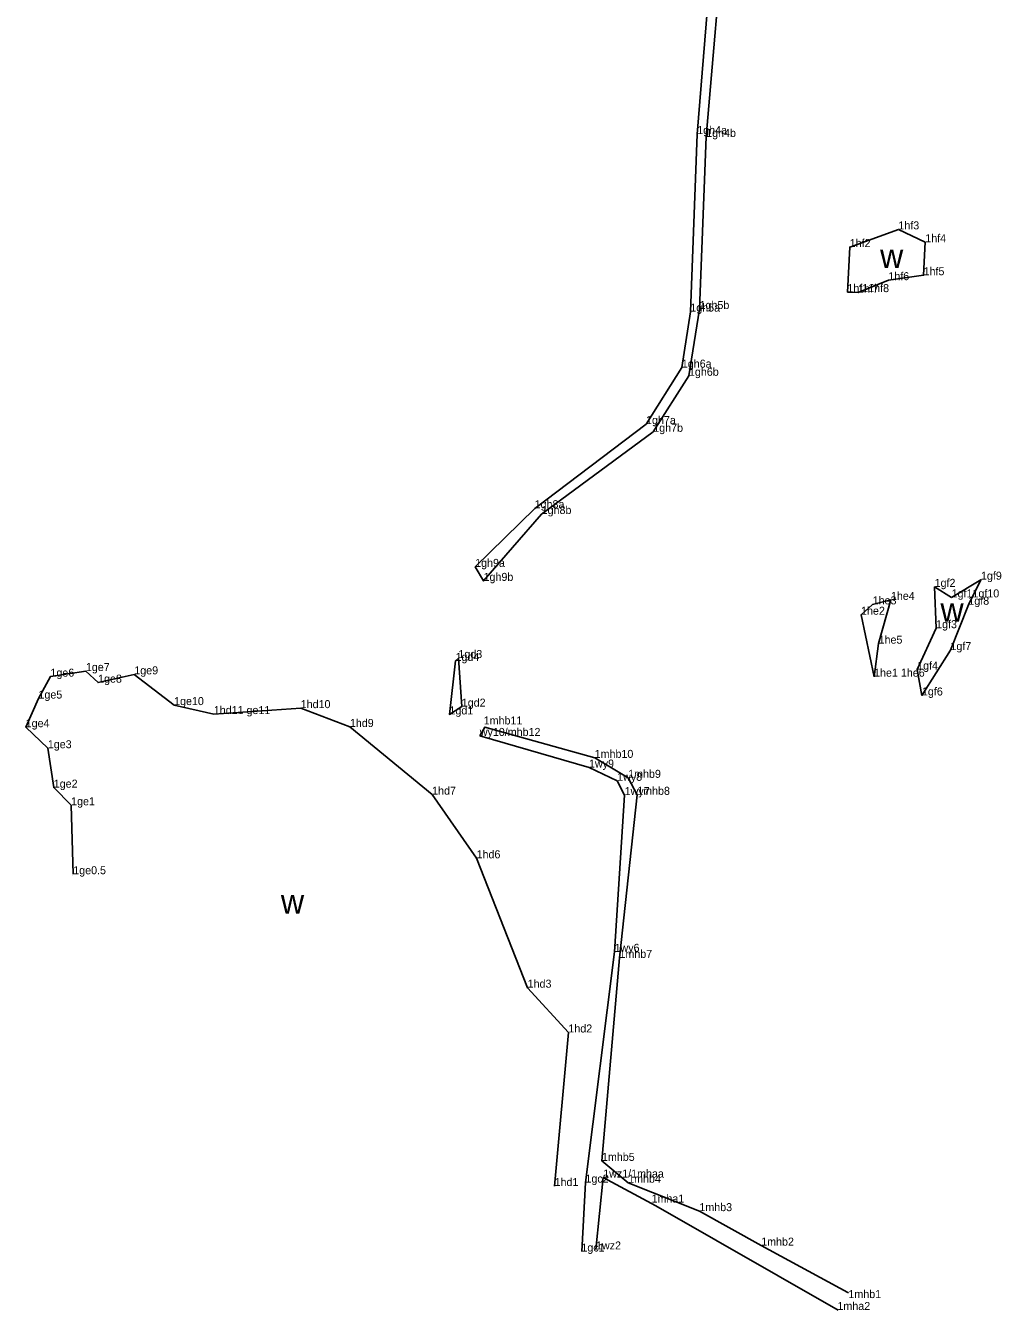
# Model space of a CAD drawing. Extents: x 2072529 to 2267990, y 436423 to 470008.
# Drawn here: x 2077727 to 2078337, y 465348 to 466151 of the extents above; entities that cross this region are included whole.
import ezdxf

# ---------------------------------------------------------------- set-up
doc = ezdxf.new("R2010")
doc.units = 0
for name, color, linetype in [('Level 3', 7, 'Continuous'), ('Old_Level_52', 7, 'Continuous'), ('Prop SS Cut Line', 7, 'Continuous')]:
    doc.layers.add(name, color=color, linetype=linetype)

msp = doc.modelspace()

# ---------------------------------------------------------------- linework, layer by layer
at = {"layer": 'Level 3'}
for p, q in [((2078147.017, 466082.829), (2078147.017, 466082.829)), ((2078152.623, 466081.039), (2078152.623, 466081.039)), ((2078272.711, 466023.278), (2078272.711, 466023.278)), ((2078242.293, 466012.251), (2078242.293, 466012.251)), ((2078289.531, 466015.284), (2078289.531, 466015.284)), ((2078266.455, 465991.543), (2078266.455, 465991.543)), ((2078288.45, 465994.628), (2078288.45, 465994.628)), ((2078240.832, 465984.093), (2078240.832, 465984.093)), ((2078247.477, 465983.811), (2078247.477, 465983.811)), ((2078148.591, 465973.437), (2078148.591, 465973.437)), ((2078142.832, 465971.82), (2078142.832, 465971.82)), ((2078137.396, 465936.903), (2078137.396, 465936.903)), ((2078141.846, 465931.823), (2078141.846, 465931.823)), ((2078115.034, 465901.653), (2078115.034, 465901.653)), ((2078119.037, 465896.835), (2078119.037, 465896.835)), ((2078045.501, 465848.946), (2078045.501, 465848.946)), ((2078049.792, 465845.721), (2078049.792, 465845.721)), ((2078008.251, 465812.431), (2078008.251, 465812.431)), ((2078013.504, 465803.681), (2078013.504, 465803.681)), ((2078324.323, 465804.431), (2078324.323, 465804.431)), ((2078295.36, 465799.956), (2078295.36, 465799.956)), ((2078256.622, 465789.009), (2078256.622, 465789.009)), ((2078268.041, 465791.806), (2078268.041, 465791.806)), ((2078305.973, 465793.375), (2078305.973, 465793.375)), ((2078316.427, 465788.775), (2078316.427, 465788.775)), ((2078249.386, 465782.532), (2078249.386, 465782.532)), ((2078296.295, 465774.131), (2078296.295, 465774.131)), ((2078260.333, 465764.471), (2078260.333, 465764.471)), ((2077997.783, 465755.481), (2077997.783, 465755.481)), ((2078305.236, 465760.447), (2078305.236, 465760.447)), ((2077764.996, 465747.36), (2077764.996, 465747.36)), ((2077995.99, 465753.665), (2077995.99, 465753.665)), ((2078284.427, 465748.27), (2078284.427, 465748.27)), ((2077742.85, 465743.86), (2077742.85, 465743.86)), ((2077772.636, 465740.106), (2077772.636, 465740.106)), ((2077795.26, 465745.292), (2077795.26, 465745.292)), ((2078257.529, 465743.833), (2078257.529, 465743.833)), ((2078287.442, 465732.081), (2078287.442, 465732.081)), ((2077735.361, 465730.162), (2077735.361, 465730.162)), ((2077820.116, 465726.099), (2077820.116, 465726.099)), ((2077899.23, 465724.183), (2077899.23, 465724.183)), ((2077999.869, 465725.139), (2077999.869, 465725.139)), ((2077844.926, 465720.475), (2077844.926, 465720.475)), ((2077992.169, 465720.238), (2077992.169, 465720.238)), ((2077727.375, 465712.289), (2077727.375, 465712.289)), ((2077929.958, 465712.402), (2077929.958, 465712.402)), ((2078014.147, 465711.893), (2078014.147, 465711.893)), ((2078011.134, 465706.809), (2078011.134, 465706.809)), ((2077741.202, 465699.117), (2077741.202, 465699.117)), ((2078082.917, 465693.114), (2078082.917, 465693.114)), ((2078079.388, 465687.07), (2078079.388, 465687.07)), ((2078096.961, 465678.769), (2078096.961, 465678.769)), ((2078103.846, 465680.644), (2078103.846, 465680.644)), ((2077744.91, 465674.501), (2077744.91, 465674.501)), ((2077981.353, 465670.127), (2077981.353, 465670.127)), ((2078101.648, 465669.862), (2078101.648, 465669.862)), ((2078109.505, 465670.024), (2078109.505, 465670.024)), ((2077755.771, 465663.491), (2077755.771, 465663.491)), ((2078009.133, 465630.349), (2078009.133, 465630.349)), ((2077756.521, 465619.827), (2077756.521, 465619.827)), ((2078095.329, 465571.93), (2078095.329, 465571.93)), ((2078098.425, 465568.163), (2078098.425, 465568.163)), ((2078041.044, 465549.527), (2078041.044, 465549.527)), ((2078066.505, 465521.543), (2078066.505, 465521.543)), ((2078087.479, 465441.318), (2078087.479, 465441.318)), ((2078077.156, 465427.738), (2078077.156, 465427.738)), ((2078088.251, 465430.9), (2078088.251, 465430.9)), ((2078103.842, 465427.69), (2078103.842, 465427.69)), ((2078057.881, 465425.614), (2078057.881, 465425.614)), ((2078118.47, 465415.307), (2078118.47, 465415.307)), ((2078148.337, 465409.925), (2078148.337, 465409.925)), ((2078186.992, 465388.379), (2078186.992, 465388.379)), ((2078074.82, 465384.71), (2078074.82, 465384.71)), ((2078083.745, 465385.964), (2078083.745, 465385.964)), ((2078241.058, 465359.194), (2078241.058, 465359.194)), ((2078235.003, 465347.974), (2078235.003, 465347.974))]:
    msp.add_line(p, q, dxfattribs=at)
at = {"layer": 'Old_Level_52'}
for points in [[(2078187.207, 466478.434), (2078174.376, 466362.169), (2078158.18, 466220.774), (2078147.017, 466082.829), (2078142.832, 465971.82), (2078137.396, 465936.903), (2078115.034, 465901.653), (2078045.501, 465848.946), (2078008.251, 465812.431), (2078013.504, 465803.681), (2078049.793, 465845.457), (2078119.546, 465896.835), (2078141.846, 465931.823), (2078148.473, 465973.539), (2078152.623, 466081.039), (2078164.441, 466219.076), (2078179.216, 466361.517), (2078194.015, 466473.907)], [(2077757.103, 465620.409), (2077755.771, 465663.491), (2077744.91, 465674.501), (2077741.202, 465699.117), (2077727.375, 465712.289), (2077735.361, 465730.162), (2077742.85, 465743.86), (2077764.996, 465747.36), (2077772.636, 465740.106), (2077795.26, 465745.292), (2077820.116, 465726.099), (2077844.926, 465720.475), (2077899.23, 465724.183), (2077929.958, 465712.402), (2077981.353, 465670.127), (2078009.133, 465630.349), (2078041.044, 465549.527), (2078066.505, 465521.543), (2078057.881, 465425.614)], [(2078241.497, 465358.925), (2078241.058, 465359.194), (2078186.992, 465388.379), (2078148.337, 465409.925), (2078103.842, 465427.69), (2078087.479, 465441.318), (2078098.425, 465568.163), (2078109.505, 465670.024), (2078103.846, 465680.644), (2078082.917, 465693.114), (2078014.354, 465712.34), (2078011.134, 465706.809)], [(2078011.134, 465706.809), (2078079.388, 465687.07), (2078096.961, 465678.769), (2078101.648, 465669.862), (2078095.329, 465571.93), (2078077.156, 465427.738), (2078074.82, 465384.71)], [(2078083.745, 465385.964), (2078088.251, 465430.9), (2078121.222, 465413.341), (2078235.003, 465347.974)]]:
    msp.add_lwpolyline(points, dxfattribs=at)
for points in [[(2078240.832, 465984.093), (2078242.293, 466012.251), (2078272.711, 466023.278), (2078289.531, 466015.284), (2078288.45, 465994.628), (2078266.455, 465991.543), (2078247.477, 465983.811)], [(2078305.973, 465793.375), (2078295.36, 465799.956), (2078296.295, 465774.131), (2078284.427, 465748.27), (2078287.442, 465732.081), (2078305.236, 465760.447), (2078316.427, 465788.775), (2078324.323, 465804.431)], [(2078257.529, 465743.833), (2078249.386, 465782.532), (2078256.622, 465789.009), (2078268.041, 465791.806), (2078260.333, 465764.471)], [(2077997.783, 465755.481), (2077995.99, 465753.665), (2077992.169, 465720.238), (2077999.869, 465725.139)]]:
    msp.add_lwpolyline(points, close=True, dxfattribs=at)

# ---------------------------------------------------------------- texts
for s, p in [('1gh4a', (2078147.017, 466082.829)), ('1gh4b', (2078152.623, 466081.039)), ('1hf3', (2078272.711, 466023.278)), ('1hf4', (2078289.531, 466015.284)), ('1hf2', (2078242.293, 466012.251)), ('1hf6', (2078266.455, 465991.543)), ('1hf5', (2078288.45, 465994.628)), ('1hf11hf8', (2078240.832, 465984.093)), ('1hf7', (2078247.477, 465983.811)), ('1gh5a', (2078142.688, 465971.942)), ('1gh5b', (2078148.473, 465973.539)), ('1gh6a', (2078137.396, 465936.903)), ('1gh6b', (2078141.846, 465931.823)), ('1gh7a', (2078115.034, 465901.653)), ('1gh7b', (2078119.546, 465896.835)), ('1gh8a', (2078045.414, 465849.069)), ('1gh8b', (2078049.793, 465845.457)), ('1gh9a', (2078008.251, 465812.431)), ('1gh9b', (2078013.504, 465803.681)), ('1gf2', (2078295.36, 465799.956)), ('1gf9', (2078324.323, 465804.431)), ('1he4', (2078268.041, 465791.806)), ('1gf11gf10', (2078305.973, 465793.375)), ('1he2', (2078249.386, 465782.532)), ('1he3', (2078256.622, 465789.009)), ('1gf8', (2078316.427, 465788.775)), ('1gf3', (2078296.295, 465774.131)), ('1he5', (2078260.333, 465764.471)), ('1gf7', (2078305.236, 465760.447)), ('1gd4', (2077995.99, 465753.665)), ('1gd3', (2077997.783, 465755.481)), ('1ge6', (2077742.85, 465743.86)), ('1ge7', (2077764.996, 465747.36)), ('1ge9', (2077795.26, 465745.292)), ('1he1 1he6', (2078257.529, 465743.833)), ('1gf4', (2078284.427, 465748.27)), ('1ge8', (2077772.636, 465740.106)), ('1ge5', (2077735.361, 465730.162)), ('1gf6', (2078287.442, 465732.081)), ('1ge10', (2077820.116, 465726.099)), ('1hd11 ge11', (2077844.926, 465720.475)), ('1hd10', (2077899.23, 465724.183)), ('1gd1', (2077992.169, 465720.238)), ('1gd2', (2077999.869, 465725.139)), ('1ge4', (2077727.375, 465712.289)), ('1hd9', (2077929.958, 465712.402)), ('1mhb11', (2078013.572, 465713.978)), ('wy10/mhb12', (2078011.134, 465706.809)), ('1ge3', (2077741.202, 465699.117)), ('1wy9', (2078079.388, 465687.07)), ('1mhb10', (2078082.917, 465693.114)), ('1wy8', (2078096.961, 465678.769)), ('1mhb9', (2078103.846, 465680.644)), ('1ge2', (2077744.91, 465674.501)), ('1hd7', (2077981.353, 465670.127)), ('1mhb8', (2078109.505, 465670.024)), ('1ge1', (2077755.771, 465663.491)), ('1wy7', (2078101.648, 465669.862)), ('1hd6', (2078009.133, 465630.349)), ('1ge0.5', (2077757.103, 465620.409)), ('1wy6', (2078095.329, 465571.93)), ('1mhb7', (2078098.425, 465568.163)), ('1hd3', (2078041.044, 465549.527)), ('1hd2', (2078066.505, 465521.543)), ('1mhb5', (2078087.479, 465441.318)), ('1wz1/1mhaa', (2078088.251, 465430.9)), ('1hd1', (2078057.881, 465425.614)), ('1gc2', (2078077.156, 465427.738)), ('1mhb4', (2078103.842, 465427.69)), ('1mha1', (2078118.47, 465415.307)), ('1mhb3', (2078148.337, 465409.925)), ('1gc1', (2078074.63, 465384.71)), ('1wz2', (2078083.745, 465385.964)), ('1mhb2', (2078186.992, 465388.379)), ('1mhb1', (2078241.468, 465355.618)), ('1mha2', (2078234.64, 465348.177))]:
    msp.add_text(s, height=5).set_placement(p)
at = {"layer": 'Prop SS Cut Line'}
for p in [(2078261.266, 465999.189), (2078298.992, 465778.148), (2077886.859, 465595.825)]:
    msp.add_text('w', height=15, dxfattribs=at).set_placement(p)

doc.saveas('drawing.dxf')
